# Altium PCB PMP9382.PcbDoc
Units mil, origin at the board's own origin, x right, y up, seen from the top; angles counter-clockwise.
Board outline 2400 x 2500 mil, 2 copper layers (Top Layer, Bottom Layer), stack 62 mil thick; 45 components, 14 nets, 79 pads, 6 vias.
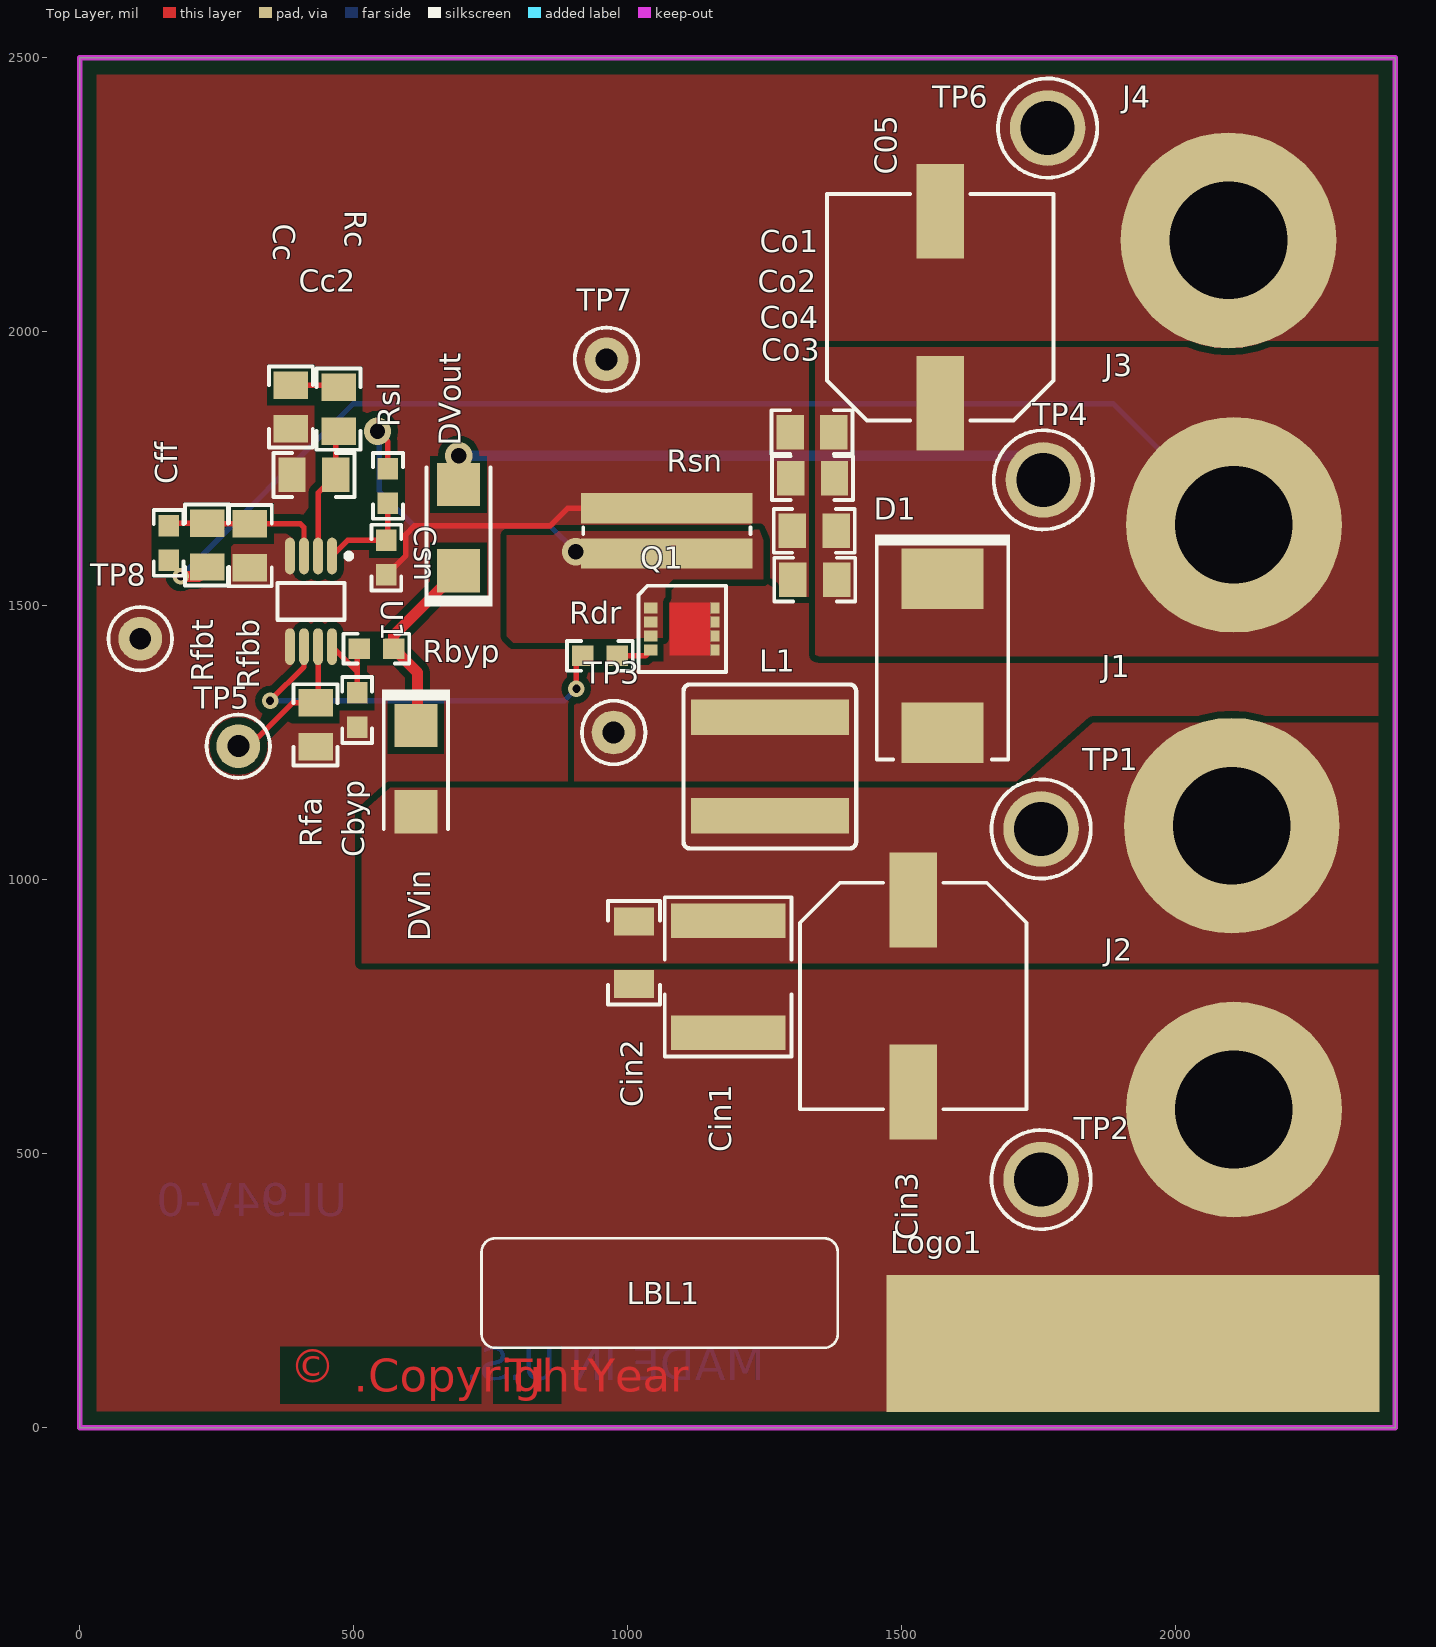
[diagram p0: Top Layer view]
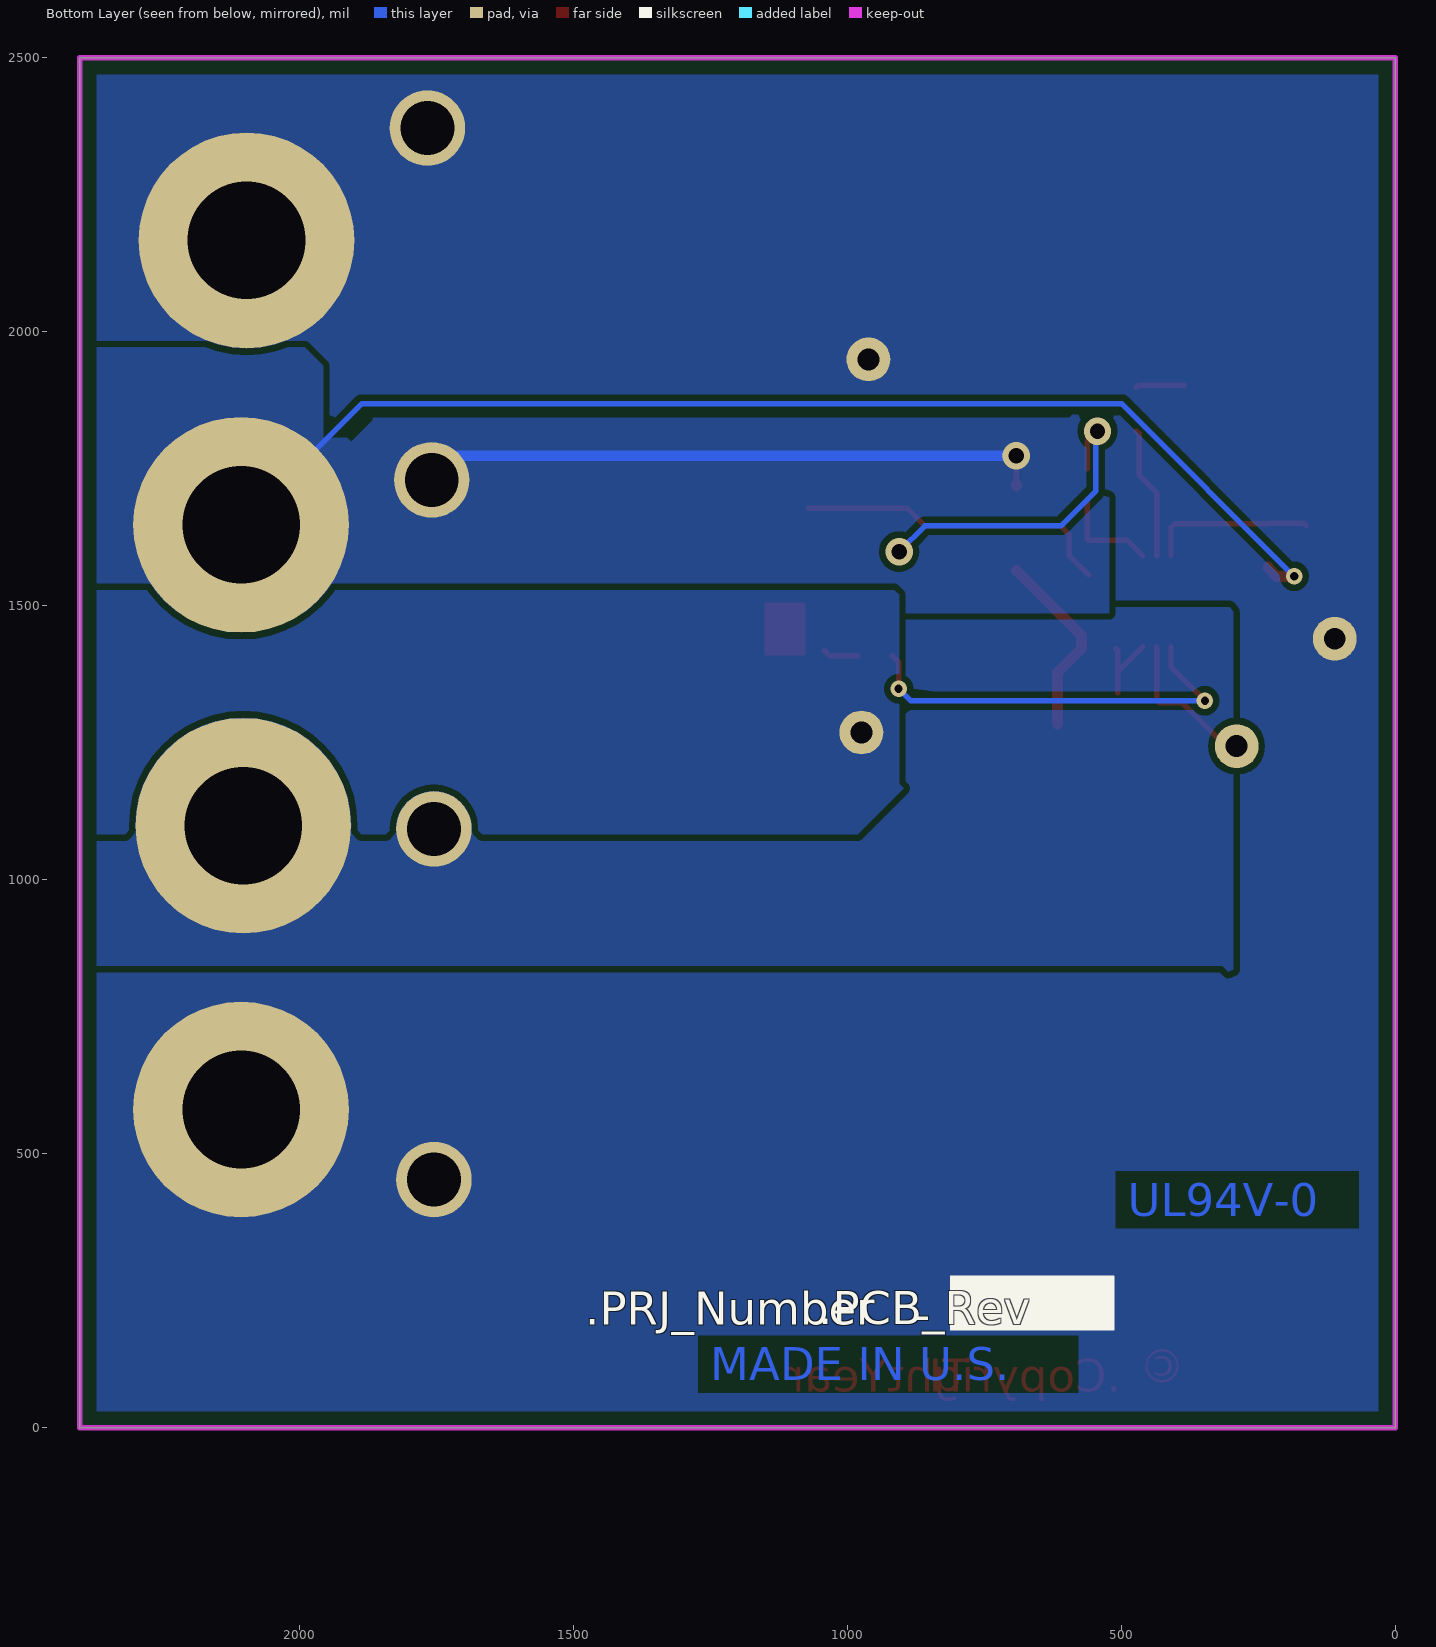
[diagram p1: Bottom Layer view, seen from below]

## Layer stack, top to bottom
Top Solder: solder mask 0.4, Solder Resist, Dk 3.5
Top Layer: signal copper 1.4
Dielectric1: core 59.2, FR-4, Dk 4.8
Bottom Layer: signal copper 1.4
Bottom Solder: solder mask 0.4, Solder Resist, Dk 3.5

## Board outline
0,0 2400,0 2400,2500 0,2500

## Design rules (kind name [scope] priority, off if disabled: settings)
AcuteAngle [All] p1: minimum=4.50000000000000E+0001 checktracksonly=FALSE
AssemblyTestPointUsage [All] p1: valid=2
Clearance Clearance_BoardEdge_MountingHoles [OnCopper and InComponentClass('Mounting Holes') vs IsKeepOut] p1: gap=30
Clearance Clearance_BoardEdge_Poly [OnCopper and InPoly vs IsKeepOut] p2: gap=25
Clearance Clearance_BoardEdge [OnCopper and Not InComponentClass('Logo') and not InComponentClass('FiducialMark') and not InRegion(1000,500,4000,800) and Not IsKeepout vs IsKeepOut] p3: gap=50
Clearance Clearance_Poly [InPolygon] p4: gap=10
Clearance [All] p5: gap=5
ComponentClearance ComponentClearance_Shunt [InComponentClass('Header') vs InComponentClass('Shunt')] p1: gap=0 collisioncheckmode=3 verticalgap=0 showdistances=FALSE
ComponentClearance ComponentClearance_Logo [InComponentClass('Logo')] p2: gap=50 collisioncheckmode=3 verticalgap=10 showdistances=FALSE
ComponentClearance ComponentClearance_ScrewToNut [(HasFootprint('NY PMS 440 0025 PH')) vs (HasFootprint('Keystone_1902C'))] p3: gap=5 collisioncheckmode=3 verticalgap=10 showdistances=FALSE
ComponentClearance ComponentClearance_MountingHoles [InComponentClass('Mounting Holes')] p4: gap=200 collisioncheckmode=3 verticalgap=100000 showdistances=FALSE
ComponentClearance ComponentClearance_SmallPassives [HasFootprint('0201*') or HasFootprint('0402*') or HasFootprint('0508') or HasFootprint('0603*') or HasFootprint('0612') or HasFootprint('0805*') or HasFootprint('0815*') or HasFootprint('0830*') or HasFootprint('1206*') or HasFootprint('1210*') or HasFootprint('1808*') or HasFootprint('1812*') or HasFootprint('1825*') or HasFootprint('2010*') or HasFootprint('2220*') or HasFootprint('2225*') or HasFootprint('2512*') or HasFootprint('2728*') or HasFootprint('3518*') vs HasFootprint('0201*') or HasFootprint('0402*') or HasFootprint('0508') or HasFootprint('0603*') or HasFootprint('0612') or HasFootprint('0805*') or HasFootprint('0815*') or HasFootprint('0830*') or HasFootprint('1206*') or HasFootprint('1210*') or HasFootprint('1808*') or HasFootprint('1812*') or HasFootprint('1825*') or HasFootprint('2010*') or HasFootprint('2220*') or HasFootprint('2225*') or HasFootprint('2512*') or HasFootprint('2728*') or HasFootprint('3518*')] p5: gap=20 collisioncheckmode=3 verticalgap=10 showdistances=FALSE
ComponentClearance ComponentClearance_THtoSMT [IsThruComponent vs IsSMTComponent] p6: gap=50 collisioncheckmode=3 verticalgap=30 showdistances=FALSE
ComponentClearance ComponentClearance_THtoTH [IsThruComponent vs IsThruComponent] p7: gap=50 collisioncheckmode=3 verticalgap=30 showdistances=FALSE
ComponentClearance [All] p8: gap=20 collisioncheckmode=3 verticalgap=10 showdistances=FALSE
DiffPairsRouting [All] p1: maxlimit=100 minlimit=10 mostfreqgap=10 toplayer_minwidth=15 toplayer_maxwidth=15 toplayer_prefwidth=15 bottomlayer_minwidth=15 bottomlayer_maxwidth=15 bottomlayer_prefwidth=15 maxuncoupledlength=1000
FabricationTestPointUsage TestPointUsage [All] p1: valid=2 allowmultiple=FALSE
FabricationTestpoint Testpoint [All] p1: side=3 testpointundercomponent=TRUE minsize=40 maxsize=100 preferedsize=60 minholesize=0 maxholesize=40 preferedholesize=32 testpointgrid=1 allowsidetop=TRUE allowsidebottom=TRUE usegrid=TRUE gridtolerance=0.01
FanoutControl Fanout_LCC [IsLCC] p1: bgadir=Out bgaviamode=Centered fanoutstyle=Auto fanoutdirection=Alternating viagrid=1 // Fanout_LCC (Default Rule)
FanoutControl Fanout_BGA [IsBGA] p2: bgadir=Out bgaviamode=Centered fanoutstyle=Auto fanoutdirection=Alternating viagrid=1 // Fanout_BGA (Default Rule)
FanoutControl Fanout_Default [All] p4: bgadir=Out bgaviamode=Centered fanoutstyle=Auto fanoutdirection=Alternating viagrid=1 // Fanout_Default (Default Rule)
FanoutControl Fanout_Small [(CompPinCount < 5)] p5: bgadir=Out bgaviamode=Centered fanoutstyle=Auto fanoutdirection=OutThenIn viagrid=1 // Fanout_Small (Default Rule)
HoleSize [All] p1: absolutevalues=TRUE maxlimit=251 minlimit=10 maxpercent=80.000 minpercent=20.000
MinimumAnnularRing MinimumAnnularRing_ThermalPadVias [IsVia and InAnyComponent] p1: minimumring=5.91
MinimumAnnularRing [All] p2: minimumring=5
MinimumSolderMaskSliver MinimumSolderMaskSliver_Logo [InComponentClass('Logo') vs InComponentClass('Logo')] p1: minsoldermaskwidth=0.7
MinimumSolderMaskSliver [All] p2: minsoldermaskwidth=3.94
PlaneConnect [All] p1: planeconnectstyle=Direct reliefexpansion=10 reliefentries=4 reliefconductorwidth=10 reliefairgap=10
PolygonConnect [All] p1: connectstyle=Direct reliefconductorwidth=10 reliefentries=4 polygonreliefangle="90 Angle" airgapwidth=10
RoutingVias ThermalPadVias [IsVia and InAnyComponent] p1: holewidth=7.87 width=19.68 viastyle="Through Hole" minholewidth=7.87 minwidth=19.68 maxholewidth=12.99 maxwidth=23.62
RoutingVias [All] p2: holewidth=16 width=34 viastyle="Through Hole" minholewidth=7.87 minwidth=26 maxholewidth=40 maxwidth=65
SMDToCorner [All] p1: distance=30000
SilkToSilkClearance [All] p1: silktosilkclearance=5
SilkToSolderMaskClearance SilkscreenOverComponentPads [IsPad] p1: minsilkscreentomaskgap=5 clearancetoexposedcopper=FALSE
SolderMaskExpansion [All] p1: expansion=1.97
UnpouredPolygon [All] p1: allowunpoured=FALSE
Width [All] p1: maxlimit=100 minlimit=6 preferedwidth=10 checkconnectedcopper=TRUE
15 further rules are at their usual default settings.

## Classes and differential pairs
component class Logo: Logo1
component class PMP9382_Hardware_ANSI-B: LBL1 Logo1 ZZ1 ZZ2 ZZ3 ZZ4
component class AssemblyNote: ZZ1 ZZ2 ZZ3 ZZ4
component class Label: LBL1
component class "PMP9382 schemaitc rev2": AA1 C05 Cbyp Cc Cc2 Cff Cin1 Cin2 Cin3 Co1 Co2 Co3 Co4 Csn D1 DVin DVout J1 J2 J3 J4 L1 Q1 Rbyp Rc Rdr Rfa Rfbb Rfbt Rsl Rsn TP1 TP2 TP3 TP4 TP5 TP6 TP7 TP8 U1

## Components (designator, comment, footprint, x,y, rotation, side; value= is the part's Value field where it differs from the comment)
C05 "16SVPE470M" CAPSMT_62_JC0 1570,2045 r90 top
Cbyp "GRM188R71C104KA01D" 0603 506,1310 r270 top
Cc "08055C104JAT2A" 0805_HV 385,1863 r270 top
Cc2 "08055A102FAT2A" 0805_HV 427,1739 r180 top
Cff "C3216X5R1E476M" 0603 162,1615 r90 top
Cin1 "C5750X5R1C476M" 2220 1183,823 r270 top
Cin2 "C3216X5R1E476M" 1206 1011,867 r270 top
Cin3 "APXA160ARA331MJC0G" CAPSMT_62_JC0 1521,788 r270 top
Co1 "EMK212BJ106KG-T" 0805_HV 1336,1817 r180 top
Co2 "EMK212BJ106KG-T" 0805_HV 1337,1733 r180 top
Co3 "EMK212BJ106KG-T" 0805_HV 1341,1548 r180 top
Co4 "EMK212BJ106KG-T" 0805_HV 1340,1637 r180 top
Csn "C0603C103K5RACTU" 0603 559,1588 r270 top
D1 "B520C-13-F" SMC 1574,1409 r270 top
DVin "MBRA210LT3G" SMA 613,1203 r270 top
DVout "MBRA210LT3G" SMA 691,1643 r90 top
J1 "575-4" Keystone_575-4 2102,1099 r0 top
J2 "575-4" Keystone_575-4 2106,581 r0 top
J3 "575-4" Keystone_575-4 2106,1648 r0 top
J4 "575-4" Keystone_575-4 2096,2167 r0 top
L1 "XAL7070-332MEB" XAL7070 1259,1207 r270 top
LBL1 "Size: 0.65\" x 0.20 \"" Label_650x200 1058,246 r0 top
Logo1 "Texas Instruments" TI_Stacked_SolderMask_Small 1922,154 r0 top
Q1 "CSD16323Q3" TRANS_NexFET_Q3 1100,1458 r0 top
Rbyp "CRCW060310R0FKEA" 0603 541,1422 r0 top
Rc "CRCW08051K30JNEA" 0805_HV 472,1859 r270 top
Rdr "CRCW06030000Z0EA" 0603 949,1409 r0 top
Rfa "CRCW080530K1FKEA" 0805_HV 430,1283 r90 top
Rfbb "CRCW080511K3FKEA" 0805_HV 310,1610 r90 top
Rfbt "CRCW080582K5FKEA" 0805_HV 232,1611 r270 top
Rsl "CRCW06030000Z0EA" 0603 562,1719 r270 top
Rsn "RL7520WT-R005-F" 3008M 1071,1637 r270 top
TP1 "Vi" Keystone1502-2 1754,1093 r0 top
TP2 "GND" Keystone1502-2 1754,453 r0 top
TP3 "SW" Keystone5000 974,1269 r0 top
TP4 "Vo" Keystone1502-2 1758,1730 r0 top
TP5 "SD" Keystone5000 289,1244 r0 top
TP6 "GND" Keystone1502-2 1766,2372 r0 top
TP7 "GND" Keystone5001 961,1950 r0 top
TP8 "GND" Keystone5001 110,1440 r0 top
U1 "LM3478QMM" MUA08A_N 421.68,1508.43 r270 top
ZZ1 "This Assembly Note is for PCB labels only" AssemblyNoteLabel 185,3938 r0 top
ZZ2 "These assemblies are ESD sensitive, ESD precautions shall be observed." AssemblyNote 185,3829.11 r0 top
ZZ3 "These assemblies must be clean and free from flux and all contaminants. Use of no clean flux is not acceptable." AssemblyNote 185,3740.56 r0 top
ZZ4 "These assemblies must comply with workmanship standards IPC-A-610 Class 2, unless otherwise specified." AssemblyNote 185,3652 r0 top

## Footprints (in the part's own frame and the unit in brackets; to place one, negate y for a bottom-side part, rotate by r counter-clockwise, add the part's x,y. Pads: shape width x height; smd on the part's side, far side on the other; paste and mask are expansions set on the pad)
0603 [mm] "0603 from SM-752 data"
  rect 1x0.95 smd: 1(-0.8,0) 2(0.8,0)
  silkscreen extent -1.52,-0.69 1.52,0.69, body extent -0.87,-0.47 0.87,0.47, height 0.85
0805_HV [mil] "0805 with 30mil clearance between pads"
  rect 50x63 smd: 1(-40,0) 2(40,0)
  silkscreen extent -74,-40 74,40, body extent -43,-29 43,29, height 43
1206 [mm] "1206 from SM-752 data"
  rect 1.3x1.85 smd: 1(-1.45,0) 2(1.45,0)
  silkscreen extent -2.4,-1.21 2.4,1.21, body extent -1.7,-0.9 1.7,0.9, height 1.35
2220 [mm] "Chip Capacitor, Body 5.7x5.0mm, IPC Medium Density"
  rect 1.6x5.3 smd: 1(-2.6,0) 2(2.6,0)
  silkscreen extent -3.69,-2.94 3.69,2.94, body extent -2.95,-2.62 2.95,2.62, height 1.35
3008M [mm] "Chip Resistor, 2-Leads, Body 2.0x7.5mm, IPC Low Density based on Susumu RL7520W dimensions."
  rect 1.4x7.95 smd: 1(-1.05,0) 2(1.05,0)
  silkscreen extent -0.15,-3.87 0.15,3.88, body extent -1.1,-3.9 1.1,3.9, height 0.6
AssemblyNote [mil] "Assembly Note"
AssemblyNoteLabel [mil] "Assembly Note for PCB Labels"
CAPSMT_62_JC0 [mm] "10 x 12.2mm:  Chemi-Con JC0"
  rect 4.4x2.2 smd: 1(-4.45,0) 2(4.45,0)
  silkscreen extent -5.25,-5.25 5.25,5.25, body extent -5.26,-5.26 5.26,5.26, height 12.7
Keystone1502-2 [mm] "Double Turret"
  round 3.5 hole 2.5: 1(0,0)
  silkscreen extent -2.3,-2.3 2.3,2.3, body extent -1.6,-1.6 1.59,1.6, height 5.62
Keystone5000 [mil] "For Keystone 500x miniature loop terminals"
  round 80 hole 40: 1(0,0)
  silkscreen extent -58,-58 58,58, body extent -49,-49 49,49, height 182
Keystone5001 [mil] "For Keystone 500x miniature loop terminals"
  round 80 hole 40: 1(0,0)
  silkscreen extent -58,-58 58,58, body extent -49,-49 49,49, height 182
Keystone_575-4 [mm] "Banana Jack"
  round 10 hole 5.45: 1(0,0)
  body extent -3.95,-3.95 3.92,3.93, height 2.36
Label_650x200 [mil] "Thermal Transfer Label"
  silkscreen extent -325,-100 325,100, body extent -326,-101 326,101, height 1
MUA08A_N [mm] "TSOP, 8-Leads, Body 3x3mm, Pitch 0.65mm, IPC Medium Density"
  oval 1.7x0.45 smd: 1(-2.1,0.975) 2(-2.1,0.325) 3(-2.1,-0.325) 4(-2.1,-0.975) 5(2.1,-0.975) 6(2.1,-0.325) 7(2.1,0.325) 8(2.1,0.975)
  silkscreen extent -2.22,-1.55 0.85,1.88, body extent -1.6,-1.6 1.6,1.6, height 1.09
SMA [mm] "Molded Diode, 2-Leads, Body 4.3x2.6mm, IPC Medium Density, based on OnSemi component dimensions and land pattern"
  rect 2x2 smd: 1(-2,0) 2(2,0)
  silkscreen extent -3.66,-1.57 2.79,1.57, body extent -2.6,-1.3 2.6,1.3, height 2.42
SMC [mil] "Molded Diode, 2-Leads, Body 6.9x5.8mm, IPC Medium Density, based on OnSemi component dimensions and land patterns"
  rect 110x150 smd: 1(-140.49,0) 2(140.49,0)
  silkscreen extent -221,-124 189,123, body extent -156,-116 156,116, height 91
TI_Stacked_SolderMask_Small [mil]
  rect 900x250 smd paste-125 mask-125: 0(0,0)
TRANS_NexFET_Q3 [mm] "TI recommended land pattern (nominal) M0143-01"
  rect 0.63x0.5 smd mask+0.076: 1(-1.49,0.975) 2(-1.49,0.325) 3(-1.49,-0.325) 4(-1.49,-0.975)
  rect 0.41x0.5 smd mask+0.076: 5(1.49,-0.975) 6(1.49,-0.325) 7(1.49,0.325) 8(1.49,0.975)
  Top Layer region: -0.615,-1.225 1.285,-1.225 1.285,1.225 -0.615,1.225
  silkscreen extent -2.05,-2 2,2, body extent -1.76,-1.7 1.66,1.7, height 1.11
XAL7070 [mm] "COILCRAFT"
  rect 1.63x7.33 smd: 1(-2.285,0) 2(2.285,0)
  silkscreen extent -3.8,-4 3.8,4, body extent -3.81,-4.01 3.81,4.01, height 7

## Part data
C05: "CAP, AL, 470uF, 16V, +/-20%, 0.01 ohm, SMD"
Cbyp: "CAP, CERM, 0.1uF, 16V, +/-10%, X7R, 0603"
Cc: "CAP, CERM, 0.1uF, 50V, +/-5%, X7R, 0805"
Cc2: "CAP, CERM, 1000pF, 50V, +/-1%, C0G/NP0, 0805"
Cff Cin2: library part Capacitor, "CAP, CERM, 47uF, 25V, X5R, 1206"
Cin1: "CAP, CERM, 47uF, 16V, +/-20%, X5R, 2220"
Cin3: "CAP, AL, 330uF, 16V, +/-20%, 0.014 ohm, SMD"
Co1 Co2 Co3 Co4: "CAP, CERM, 10uF, 16V, +/-10%, X5R, 0805"
Csn: "CAP, CERM, 0.01uF, 50V, +/-10%, X7R, 0603"
D1: "Diode, Schottky, 20V, 5A, SMC"
DVin DVout: "Diode, Schottky, 10V, 2A, SMA"
J1 J2 J3 J4: "Standard Banana Jack, Uninsulated, 5.5mm"
L1: "Inductor, Shielded, Composite, 3.3uH, 15.1A, 0.01 ohm, SMD"
LBL1: library part THT-14-423-10, "Thermal Transfer Printable Labels, 0.650\" W x 0.200\" H - 10,000 per roll"
Logo1: library part TI_Logo, "Texas Instrument Corporate Signature"
Q1: "MOSFET, N-CH, 25V, 60A, SON 3.3x3.3mm"
Rbyp: library part CRCW060310r0FKEA, "RES, 10.0 ohm, 1%, 0.1W, 0603"
Rc: "RES, 1.3k ohm, 5%, 0.125W, 0805"
Rdr Rsl: "RES, 0 ohm, 5%, 0.1W, 0603"
Rfa: "RES, 30.1k ohm, 1%, 0.125W, 0805"
Rfbb: "RES, 11.3k ohm, 1%, 0.125W, 0805"
Rfbt: "RES, 82.5k ohm, 1%, 0.125W, 0805"
Rsn: library part RL7520WT-R010-F, "RES, 0.005 ohm, 1%, 2W, 3008"
TP1 TP2 TP4 TP6: library part 1502-2, "Terminal, Turret, TH, Double"
TP3 TP5: library part 5000, "Test Point, TH, Miniature, Red"
TP7 TP8: library part 5001, "Test Point, TH, Miniature, Black"
U1: "High Efficiency Low-Side N-Channel Controller for Switching Regulator, Automotive Grade 1, 8-pin MSOP"
ZZ1: library part AssemblyNoteLabel
ZZ2 ZZ3 ZZ4: library part AssemblyNote

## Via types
v1: diameter 30, hole 15, Top Layer to Bottom Layer, 3 vias
v2: diameter 50, hole 28, Top Layer to Bottom Layer, 3 vias

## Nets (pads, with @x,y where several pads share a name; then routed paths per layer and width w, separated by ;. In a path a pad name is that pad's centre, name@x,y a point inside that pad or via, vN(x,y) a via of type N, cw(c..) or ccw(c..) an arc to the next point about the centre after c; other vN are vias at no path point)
COMP: Cc2.1 Rc.2 U1.2 | length 243.4
  Top Layer w10: U1.2 434.48,1706.48 Cc2.1 467,1814 Rc.2
DR: Rdr.1 U1.6 | length 757.3
  Top Layer w10: v1(347,1327) 408.89,1388.89 U1.6 ; v1(906,1349) 906,1397.5 Rdr.1
  Bottom Layer w10: v1(347,1327) 884,1327 v1(906,1349)
FA: Rfa.2 TP5.1 U1.7 | length 278.3
  Top Layer w10: TP5.1 306,1261 326.25,1261 388.25,1323 Rfa.2 434.48,1327.48 U1.7
FB: Cff.2 Rfbb.2 Rfbt.1 U1.3 | length 304
  Top Layer w10: Cff.2 166.5,1651 Rfbt.1 233,1650 Rfbb.2 402,1650 408.89,1643.11 U1.3
GATE: Q1.4 Rdr.2 | length 64.7
  Top Layer w10: Rdr.2 1031.98,1409 Q1.4@1041.34,1418.36
GND: C05.2 Cbyp.2 Cc2.2 Cc.2 Cin1.2 Cin2.2 Cin3.2 Co1.2 Co2.2 Co3.2 Co4.2 Csn.2 J2.1 J4.1 Logo1.0 Rfa.1 Rfbb.1 Rsn.1 TP2.1 TP6.1 TP7.1 TP8.1 U1.4 U1.5 | length 585
  Top Layer w10: Csn.2 594.7,1592.2 594.7,1630.7 610,1646 858,1646 890.34,1678.34 Rsn.1
ISEN: Csn.1 Rsl.2 U1.1 | length 179.9
  Top Layer w10: U1.1 488.46,1619.5 Csn.1 562,1622.5 Rsl.2
NetCc_1: Cc.1 Rc.1 | length 88.7
  Top Layer w10: Cc.1 468,1903 Rc.1
NetDVin_1: DVin.1 DVout.1 Rbyp.2 | length 350.9
  Top Layer w10: DVin.1 DVin.1@616,1284.74
  Top Layer w20: DVin.1@616,1284.74 616,1378.5 Rbyp.2 572.5,1445.76 DVout.1
RSEN: Q1.1 Q1.2 Q1.3 Rsl.1 Rsn.2 | length 583.7
  Top Layer w10: v2(543,1819) 562,1800 Rsl.1
  Bottom Layer w10: v2@538,1809 546,1801 546,1710 610,1646 858,1646 v2(905,1599)
SW: D1.2 L1.1 Q1.5 Q1.6 Q1.7 Q1.8 TP3.1
VIN: Cin1.1 Cin2.1 Cin3.1 DVin.2 J1.1 L1.2 TP1.1
VIN-PIN: Cbyp.1 Rbyp.1 U1.8 | length 146.5
  Top Layer w10: U1.8@460.33,1425.75 506,1380.09 ; Cbyp.1 506,1380.09 ; Rbyp.1 506,1418.5 506,1380.09
VOUT: C05.1 Cff.1 Co1.1 Co2.1 Co3.1 Co4.1 D1.1 DVout.2 J3.1 Rfbt.2 TP4.1 | length 3340.1
  Top Layer w10: DVout.2 v2(691,1774)
  Top Layer w20: v1(184,1553.98) 216.28,1553.98 232,1569.69 Rfbt.2 ; DVout.2@691,1719 DVout.2
  Bottom Layer w10: v1(184,1553.98) 499.02,1869 1885,1869 J3.1
  Bottom Layer w20: v2(691,1774) 1714,1774 TP4.1

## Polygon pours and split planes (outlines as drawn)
GND on Top Layer "Top Layer-No Net" (solid, remove dead copper, pour order 4): 2396,836 1,836 0,835 0,0 2400,0 2400,835
VIN on Top Layer "Top Layer-No Net 1" (solid, pour order 6): 2371.07,1287 1848.37,1287 1841.46,1280.88 1714.24,1168.09 1677.75,1168.09 566.27,1168.09 518.93,1126.13 514,1121.75 514,824.49 523.86,815.74 533.72,807 2376,807 2376,1281.75 2374.03,1283.5
VOUT on Top Layer "Top Layer-No Net 2" (solid, pour order 10): 1342,1972 1342,1402 1339,1399 1348,1408 2399,1408 2399,1947 2400,1948 2376,1972 1340,1972
RSEN on Top Layer "Top Layer-No Net 3" (solid, pour order 16): 779,1632 779,1444.61 779.62,1443.99 790.61,1433 1033,1433 1056,1433 1057,1434 1068,1434 1068,1533.74 1071,1536.74 1082.68,1548.42 1247.18,1548.42 1247.18,1634.82 1237,1645 1228,1636 780,1636 780,1631 779,1630
SW on Top Layer "Top Layer-No Net 4" (solid, remove dead copper, pour order 18): 885.82,1433 902,1416.82 902,1145 2331,1145 2396,1080 2392,1084 2392,1576 886,1576 883,1573 889.02,1566.98 889.02,1436.27
GND on Top Layer "Top Layer-No Net 5" (solid, remove dead copper, pour order 20): 0,2500 0,638 19,659.22 2392,659.22 2392,2491.06 2400,2500 0,2500
SW on Bottom Layer "Bottom Layer-No Net" (solid, pour order 22): 905,1533 905,1175 897,1167 981,1083 2397,1083 2397,1459 2396,1460 2396,1529 914,1529 909,1534
VOUT on Bottom Layer "Bottom Layer-No Net 1" (solid, remove dead copper, pour order 24): 511,1849 522,1838 522,1487 2401,1487 2404,1490 2392,1502 2392,1972 1990,1972 1978,1960 1956,1938 1956,1807 1912,1807 1905,1800 1866,1839 1866,1843 595,1843 594,1844 589,1849 512,1849
VIN on Bottom Layer "Bottom Layer-No Net 2" (solid, remove dead copper, pour order 26): 302,1498 2337,1498 2392,1443 2373,1424 2373,843 315,843 295,823 295,1489
GND on Bottom Layer "Bottom Layer-No Net 3" (solid, remove dead copper, pour order 28): 0,2500 2381,2500 2392,2489 2392,8 6,8 3,11 0,14 0,2495

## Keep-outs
Keep-Out Layer:
  the board outline again, w10
  text ".Layer_Name" at 577,-858.49 h60

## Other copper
Top Layer:
  text ".CopyrightYear" at 500,66 h60
  text "TI" at 776,66 h60
  text "©" at 383,62.48 h105
  text ".Layer_Name" at 577,-858.49 h60
Bottom Layer:
  text "UL94V-0" at 488,386 h60
  text "MADE IN U.S." at 1250,86.5 h60
  text ".Layer_Name" at 577,-858.49 h60

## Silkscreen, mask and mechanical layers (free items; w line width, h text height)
Top Overlay:
  text ".Layer_Name" at 577,-858.49 h60
Bottom Overlay:
  rectangle: 512,178 812,278
  text ".PCB_Rev" at 1053,189 h60
  text ".PRJ_Number" at 1478,188 h60
  text "-" at 877,177.5 h60
  text ".Layer_Name" at 577,-858.49 h60
Top Paste:
  text ".Layer_Name" at 577,-858.49 h60
Bottom Paste:
  text ".Layer_Name" at 577,-858.49 h60
Top Solder:
  text ".Layer_Name" at 577,-858.49 h60
  text ".Layer_Name" at 577,-858.49 h60
Bottom Solder:
  text ".Layer_Name" at 577,-858.49 h60
Drill Guide:
  text ".Layer_Name" at 577,-858.49 h60
M1 Board Outline:
  lines w10: 0,0 0,2500 2400,2500 2400,394.38 2400,0 0,0
  text ".Layer_Name" at 577,-858.49 h60
M2 Board Dimensions:
  rectangle: -0.5,-285.5 124.5,-160.5
  rectangle: 124.5,-410.5 499.5,-285.5
  lines w7: -0.5,-285.5 999.5,-285.5 ; 124.5,-410.5 124.5,-160.5 ; 249.5,-410.5 249.5,-160.5 ; 499.5,-410.5 499.5,-160.5 ; 749.5,-410.5 749.5,-160.5 ; -0.5,-410.5 999.5,-410.5 999.5,-160.5 -0.5,-160.5 -0.5,-410.5
  lines w10: -0.5,-475.5 -0.5,-455.5 ; 59.5,-485.5 -0.5,-465.5 ; 59.5,-445.5 -0.5,-465.5 ; 223.58,-465.5 -0.5,-465.5 ; 775.42,-465.5 999.5,-465.5 ; 939.5,-485.5 999.5,-465.5 ; 939.5,-445.5 999.5,-465.5 ; 999.5,-475.5 999.5,-455.5
  text "1000 (mil)" at 233.58,-501.49 h60
  text ".Layer_Name" at 577,-858.49 h60
M3 3D STEP Top:
  text ".Layer_Name" at 577,-858.49 h60
M4 3D STEP Bottom:
  text ".Layer_Name" at 577,-858.49 h60
M5 Assembly Top:
  lines w10: -292,-930.17 6308,-930.17 ; -292,-726.83 6310,-726.83 ; -292,-523.5 -292,-1133.5 3713,-1133.5 6310,-1133.5 6310,-523.5 -291.5,-523.5 -291.5,-1133.5 1284,-1133.5 ; 2173,-1133.5 2173,-523.5 ; 3440,-726.83 3440,-523.5 ; 4280,-726.83 4280,-523.5 ; 4902,-1140 4902,-937.17
  text "COMPONENTS MARKED 'DNP' SHOULD NOT BE POPULATED." at 1153.5,-318.5 h60
  text "ASSEMBLY VARIANT:" at 1153,-434 h60
  text ".VariantName" at 2189,-434 h60
  text "PCB VIEWED FROM TOP SIDE" at -228.5,-655.67 h60
  text "BOARD #:" at 2248,-655.67 h60
  text ".PRJ_Number" at 2793.5,-655.67 h60
  text "REV:" at 3638,-655.67 h60
  text ".PCB_Rev" at 3929.5,-655.67 h60
  text "SVN REV:" at 4476,-655.67 h60
  text ".VersionControl_RevNumber" at 4982,-655.67 h60
  text "IGNORE ->" at -228.5,-858.49 h60
  text "PLOT NAME =" at -228.5,-1064.34 h60
  text ".plot_File_Name" at 577,-1064.34 h60
  text "GENERATED    :" at 2250,-1064.34 h60
  text ".Print_Date" at 3119.5,-1064.34 h60
  text ".Print_Time" at 3848.5,-1064.34 h60
  text "TEXAS INSTRUMENTS" at 5113,-1064.34 h60
M6 Assembly Bottom:
  lines w10: -292.5,-727.33 6309.5,-727.33 ; -290.5,-930.67 6309.5,-930.67 ; 1115.5,-1140.5 1115.5,-937.67 ; 1737.5,-727.33 1737.5,-524 ; 2577.5,-727.33 2577.5,-524 ; 3844.5,-1134 3844.5,-524 ; 4733.5,-1134 6309,-1134 6309,-524 -292.5,-524 -292.5,-1134 2304.5,-1134 6309.5,-1134 6309.5,-524
  text "COMPONENTS MARKED 'DNP' SHOULD NOT BE POPULATED." at 6102,-318 h60
  text ".VariantName" at 5058,-434 h60
  text "ASSEMBLY VARIANT:" at 6097,-434 h60
  text ".VersionControl_RevNumber" at 1035.5,-656.17 h60
  text "SVN REV:" at 1541.5,-656.17 h60
  text ".PCB_Rev" at 2088,-656.17 h60
  text "REV:" at 2379.5,-656.17 h60
  text ".PRJ_Number" at 3224,-656.17 h60
  text "BOARD #:" at 3769.5,-656.17 h60
  text "PCB VIEWED FROM BOTTOM SIDE" at 6246,-656.17 h60
  text "IGNORE ->" at 2547.85,-858.49 h60
  text "TEXAS INSTRUMENTS" at 904.5,-1064.84 h60
  text ".Print_Time" at 2169,-1064.84 h60
  text ".Print_Date" at 2898,-1064.84 h60
  text "GENERATED    :" at 3767.5,-1064.84 h60
  text ".plot_File_Name" at 5440.5,-1064.84 h60
  text "PLOT NAME =" at 6246,-1064.84 h60
M9 Title Sheet:
  drawing of 57 lines, arcs and shapes, not listed
  text "1" at 739.84,8036.5 h70
  text "2" at 3235.5,8036.5 h70
  text "3" at 5724.84,8036.5 h70
  text "4" at 8231.51,8036.5 h70
  text "5" at 10730.5,8036.5 h70
  text "6" at 13235.5,8036.5 h70
  text "A" at -416.5,6893.5 h70
  text "A" at 14383.5,6893.5 h70
  text "B" at -416.5,4513.5 h70
  text "B" at 14383.5,4513.5 h70
  text "C" at -416.5,2138.5 h70
  text "C" at 14383.5,2138.5 h70
  text "PROJECT TITLE:" at 11343.5,277.5 h45
  text ".PRJ_Title" at 11393.5,144.17 h70
  text "DESIGNED FOR:" at 11343.5,-23.5 h45
  text ".PRJ_Customer" at 11393.5,-163.5 h70
  text "D" at -416.5,-231.5 h70
  text "D" at 14383.5,-231.5 h70
  text "FILE NAME:" at 11343.5,-323.5 h45
  text ".PCB_File_Name_No_Path" at 11393.5,-443.5 h70
  text "Texas Instruments (TI) and/or its licensors do not warrant the accuracy or completeness of this specification" at 6374,-605.34 h45
  text "ENGINEER:" at 11343.5,-613.5 h45
  text "LAYOUT BY:" at 12848.5,-613.5 h45
  text "or any information contained therein. TI and/or its licensors do not warrant that this design will meet" at 6329.01,-718 h45
  text ".PRJ_Engineer" at 11393.5,-768.49 h70
  text ".PCB_Layout" at 12899,-768.49 h70
  text "the specifications, will be suitable for your application or fit for any particular purpose, or will operate in" at 6329.01,-830.67 h45
  text ".Layer_Name" at 577,-858.49 h60
  text "ALTIUM DESIGNER VERSION:" at 12848.5,-923.5 h45
  text "an implementation. TI and/or its licensors do not warrant that the design is production worthy. You should" at 6329.01,-943.33 h45
  text "completely validate and test your design implementation to confirm the system functionality for your application." at 6374,-1056 h45
  text ".print_Scale" at 11393.5,-1056.83 h70
  text ".Application_BuildNumber" at 12899,-1056.83 h70
  text "1" at 739.84,-1263.5 h70
  text "2" at 3235.5,-1263.5 h70
  text "3" at 5724.84,-1263.5 h70
  text "4" at 8231.51,-1263.5 h70
  text "5" at 10730.5,-1263.5 h70
  text "6" at 13235.5,-1263.5 h70
M10 Fab Notes:
  drawing of 212 lines, arcs and shapes, not listed
  text "DESIGN INFORMATION" at 12381.02,6810 h60
  text "(REFER ALSO ARRAY/PANEL PROFILING INFORMATION)" at 12019.46,6648.29 h60
  text "BOARD SIZE" at 11333.46,6644 h60
  text "2500MIL" at 11795.78,6516.18 h60
  text "X" at 12301.46,6516.18 h60
  text "2400MIL" at 12532.78,6516.18 h60
  text "Number of Layers :" at 11736.46,6319 h60
  text "2" at 12831.27,6309 h60
  text "MIN. TRACK WIDTH:" at 11736.46,6180 h60
  text "8" at 12832.7,6180 h60
  text "MIL" at 12987.46,6180 h60
  text "MIN. CLEARANCE:" at 11736.46,6048 h60
  text "8" at 12832.7,6048 h60
  text "MIL" at 12987.46,6048 h60
  text "MIN. VIA PAD SIZE:" at 11736.46,5916 h60
  text "20" at 12802.71,5916 h60
  text "MIL" at 12987.46,5916 h60
  text "0.05mm (2MIL)" at 12431.46,5774.29 h60
  text "MINIMUM ANNULAR RING" at 11407.23,5770 h60
  text "EXTERNAL" at 13139.46,5770 h60
  text "PER" at 11607.23,5652 h60
  text "IPC-D-275 CLASS 2 LEVEL C" at 11827.23,5652 h60
  text "MIL, HOLES" at 13315.46,5539.71 h60
  text "+/-" at 12923,5539 h60
  text "+/-" at 13777,5539 h60
  text "REGISTRATION TOLERANCES:" at 11407.23,5534 h60
  text "METAL" at 12607,5534 h60
  text "5" at 13183.2,5534 h60
  text "3" at 14016.2,5534 h60
  text "MIL" at 14132.46,5534 h60
  text "MATERIAL:" at 11332.46,5324.54 h60
  text "FR-4 High Tg" at 12318.9,5184.21 h60
  text "FR-408" at 11753.46,5175.64 h60
  text "X" at 12165.46,5175.64 h60
  text "OTHER" at 13241.46,5175.64 h60
  text "62 MIL (1.6mm) +/-10%" at 12073.56,5012.92 h60
  text "THICKNESS:" at 11407.23,5008.64 h60
  text "X" at 11945.4,5008.64 h60
  text "OTHER" at 13358.46,5008.64 h60
  text "TOLERANCE:" at 11407.23,4850.64 h60
  text "X" at 12246.53,4850.64 h60
  text "ANSI IPC-6012 TYPE 3 CLASS 2" at 12433.48,4850.64 h60
  text "OTHER +/-" at 12433.46,4694.64 h60
  text "BOW & TWIST:" at 11407.23,4537.64 h60
  text "X" at 12246.53,4537.64 h60
  text "ANSI IPC-6012 TYPE 3 CLASS 2" at 12433.48,4537.64 h60
  text "OTHER +/-" at 12433.46,4379.13 h60
  text "COPPER THICKNESS (FINISHED):" at 11332.46,4243.64 h60
  text "1.4MIL (1oz)" at 12212.46,4090.92 h60
  text "2MIL (1.4oz)" at 12979.46,4090.92 h60
  text "2.8MIL (2oz)" at 13706.46,4090.92 h60
  text "OUTER:" at 11689.46,4086.64 h60
  text "X" at 12084,4086 h60
  text "1.4MIL (1oz)" at 12212.46,3933.92 h60
  text "2.8MIL (2oz)" at 12979.46,3933.92 h60
  text "N/A" at 13706,3934.29 h60
  text "INNER SIGNAL:" at 11400.38,3929.64 h60
  text "X" at 12085.42,3929.64 h60
  text "DRILLING:" at 11332.46,3790.64 h60
  text "REFERENCE:" at 11407.23,3673.64 h60
  text "X" at 12055.46,3673.64 h60
  text "AS SHOWN" at 12242.46,3673.64 h60
  text "X" at 12956.46,3673.64 h60
  text "NC_DRILL FILES" at 13093.46,3673.64 h60
  text "PTH MIN COPPER THICKNESS:" at 11407.23,3515.64 h60
  text "X" at 12757.46,3515.64 h60
  text "1MIL" at 12894.46,3515.64 h60
  text "OTHER" at 13391.46,3515.64 h60
  text "BOARD FINISH:" at 11332.46,3356.64 h60
  text "SILKSCREEN:" at 11487.68,3238.64 h60
  text "X" at 12436.46,3238.64 h60
  text "TOP" at 12562.46,3238.64 h60
  text "X" at 12946.46,3238.64 h60
  text "BOTTOM" at 13073.46,3238.64 h60
  text "SILKSCREEN COLOR:" at 11487.68,3071.64 h60
  text "X" at 12435.42,3071.64 h60
  text "WHITE" at 12562.46,3071.64 h60
  text "OTHER" at 13073.46,3071.64 h60
  text "SOLDER RESIST COLOR:" at 11487.68,2901.64 h60
  text "X" at 12055.42,2742.44 h60
  text "GREEN" at 12182.46,2742.44 h60
  text "BLUE" at 12773.46,2742.44 h60
  text "OTHER" at 13311.46,2742.44 h60
  text "IMMERSION GOLD (ENIG)" at 12393.46,2553.92 h60
  text "ENEPIG" at 13731,2550.64 h60
  text "SURFACE FINISH:" at 11332.46,2549.64 h60
  text "IMM. TIN/SILVER OR EQUIV" at 11662,2392.64 h60
  text "OTHER" at 13093.46,2392.64 h60
  text "X" at 11506,2386 h60
  text "X" at 12207,2216 h60
  text "ARRAY/PANEL:" at 11332.46,2213.64 h60
  text "CUT AND TRIM PER MECH LAYER 1" at 12393.46,2209.35 h60
  text "N.C. ROUTE" at 12393.46,2057.64 h60
  text "V. SCORE" at 13259.46,2057.64 h60
  text "CERTIFICATION:" at 11332.46,1920.64 h60
  text "MATERIALS AND WORKMANSHIP FOR ALL PCBS" at 12057.46,1920.64 h60
  text "TO MEET OR EXCEED THE REQUIREMENTS OF:" at 12057.46,1822.64 h60
  text "X" at 11683.96,1686.13 h60
  text "ANSI IPC-A-600F CLASS ->" at 11822.96,1686.13 h60
  text "X" at 13462.02,1686.13 h60
  text "2" at 13580.96,1686.14 h60
  text "1" at 13265.96,1684.64 h60
  text "3" at 13934.96,1684.64 h60
  text "X" at 11686.02,1526.64 h60
  text "UL 94V-0" at 11822.96,1526.64 h60
  text "X" at 12498.02,1526.64 h60
  text "RoHS" at 12634.96,1526.64 h60
  text "OTHER" at 13279.36,1526.64 h60
  text "PER ORDER" at 13676.42,1526.64 h60
  text "ADDITIONAL REQUIREMENTS:" at 11332.46,1385.64 h60
  text "MICROSECTION:" at 11407.23,1270.64 h60
  text "YES" at 12312.96,1270.64 h60
  text "REQUIRED" at 13174.46,1114.49 h60
  text "BARE BOARD ELEC. TEST:" at 11407.23,1111.64 h60
  text "NONE" at 12712.96,1111.64 h60
  text "X" at 13641,1112 h60
  text "PER ORDER" at 13766.46,1111.64 h60
  text "MANUFACTURER'S UL:" at 11407.23,954.64 h60
  text "RAIL" at 12572.96,950.35 h60
  text "METAL" at 13064.77,950.35 h60
  text "X" at 13440,950 h60
  text "SILK" at 13576.46,950.35 h60
  text ".Layer_Name" at 577,-858.49 h60
M11 Gerber Information:
  lines w10: -292,-930.17 6308,-930.17 ; -292,-726.83 6310,-726.83 ; -292,-523.5 -292,-1133.5 3713,-1133.5 6310,-1133.5 6310,-523.5 -291.5,-523.5 -291.5,-1133.5 1284,-1133.5 ; 2173,-1133.5 2173,-523.5 ; 3440,-726.83 3440,-523.5 ; 4280,-726.83 4280,-523.5 ; 4902,-1140 4902,-937.17
  text "ALL ARTWORK VIEWED FROM TOP SIDE" at -228.5,-655.67 h60
  text "BOARD #:" at 2248,-655.67 h60
  text ".PRJ_Number" at 2793.5,-655.67 h60
  text "REV:" at 3638,-655.67 h60
  text ".PCB_Rev" at 3929.5,-655.67 h60
  text "SVN REV:" at 4476,-655.67 h60
  text ".VersionControl_RevNumber" at 4982,-655.67 h60
  text "LAYER NAME =" at -228.5,-858.49 h60
  text "PLOT NAME =" at -228.5,-1064.34 h60
  text ".plot_File_Name" at 577,-1064.34 h60
  text "GENERATED    :" at 2250,-1064.34 h60
  text ".Print_Date" at 3119.5,-1064.34 h60
  text ".Print_Time" at 3848.5,-1064.34 h60
  text "TEXAS INSTRUMENTS" at 5113,-1064.34 h60
M12 Stackup:
  lines w6: 11360,7460 13910,7460 ; 11360,7564.4 13910,7564.4 ; 11300,6975 ccw(c11334,6975) 11334,6941 13936,6941 ccw(c13936,6975) 13970,6975 13970,7681 ccw(c13936,7681) 13936,7715 11334,7715 ccw(c11334,7681) 11300,7681 11300,6975
  text "The Stackup Legend below this is static." at 11605.5,7874.5 h60
  text "If you change the stackup, update the Legend." at 11615.5,7784.5 h60
  text "Layer Stack Up Detail for: Ref_Design.PcbDoc" at 11360,7597.1 h57
  text "Layer" at 11360,7525.4 h24
  text "Gerber" at 12255.81,7525.4 h24
  text "Copper" at 12819.33,7525.4 h24
  text "Dielectric" at 13422.04,7525.4 h24
  text "Name" at 11360,7477.4 h24
  text "Document" at 12255.81,7477.4 h24
  text "Thickness" at 12819.33,7477.4 h24
  text "Material" at 13422.04,7477.4 h24
  text "Top Solder Mask" at 11360,7384.44 h34
  text "(.GTS)" at 12255.81,7384.44 h34
  text "Solder Resist" at 13422.04,7384.44 h34
  text "Top Layer" at 11360,7287.69 h34
  text "(.GTL)" at 12255.81,7287.69 h34
  text "1.4mil" at 12819.33,7287.69 h34
  text "FR-4" at 13422.04,7239.31 h34
  text "Bottom Layer" at 11360,7190.94 h34
  text "(.GBL)" at 12255.81,7190.94 h34
  text "1.4mil" at 12819.33,7190.94 h34
  text "Bottom Solder Mask" at 11360,7094.19 h34
  text "(.GBS)" at 12255.81,7094.19 h34
  text "Solder Resist" at 13422.04,7094.19 h34
  text ".Layer_Name" at 577,-858.49 h60
M13 Component Bodies Top:
  text ".Layer_Name" at 577,-858.49 h60
M14 Component Bodies Bottom:
  text ".Layer_Name" at 577,-858.49 h60
M15 Courtyards Top:
  text ".Layer_Name" at 577,-858.49 h60
M16 Courtyards Bottom:
  text ".Layer_Name" at 577,-858.49 h60
Drill Drawing:
  text ".legend" at 2752.5,339.5 h60
  text "Drill Table" at 2777.5,154.5 h60
  text ".Layer_Name" at 577,-858.49 h60

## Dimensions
2400,0 to 0,0 on M2 Board Dimensions
0,0 to 0,2500 on M2 Board Dimensions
